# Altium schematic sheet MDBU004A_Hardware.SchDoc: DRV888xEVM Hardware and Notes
size 431 x 279 mm; Date: Not shown in title block; ApprovedBy: Not shown in title block; CheckedBy: Not shown in title block; Author: Not shown in title block; CompanyName: Not shown in title block; DrawnBy: Rick Duncan; Engineer: Not shown in title block; Organization: Not shown in title block; Address1: Not shown in title block; Address2: Not shown in title block; Address3: Not shown in title block; Address4: Not shown in title block; DocumentNumber: 1; Revision: Use project parameter SCH_Rev; SheetNumber: 3; SheetTotal: 3; PageSetup: Record=PageOptions¦CenterHorizontal=True¦CenterVertical=True¦PrintScale=1.00¦XCorrection=1.00¦YCorrection=1.00¦PrintKind=0¦BorderSize=5000000¦LeftOffset=0¦BottomOffset=0¦Orientation=2¦PaperLength=1000¦PaperWidth=1000¦Scale=100¦PaperSource=15¦PrintQuality=600¦MediaType=1¦DitherType=10¦PaperKind=Letter¦PrintScaleMode=1
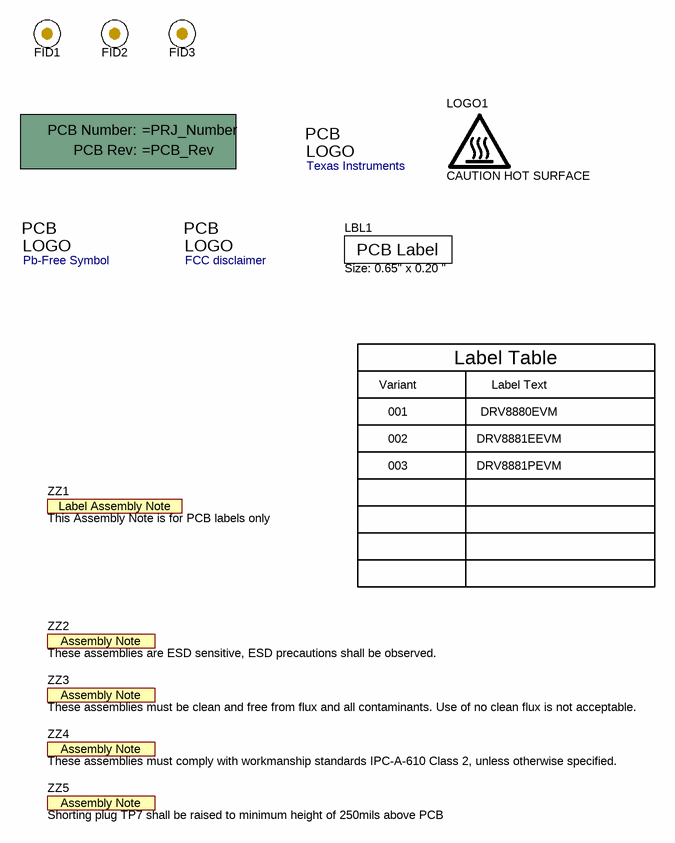
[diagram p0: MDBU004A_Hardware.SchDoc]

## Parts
!PCB1  Printed Circuit Board  (value not drawn)  (mechanical)
FID1  Fiducial  [Fiducial10-20]  (value not drawn)
FID2  Fiducial  [Fiducial10-20]  (value not drawn)
FID3  Fiducial  [Fiducial10-20]  (value not drawn)
LBL1  Size: 0.65" x 0.20 "  [Label_650x200]
LOGO1  CAUTION HOT SURFACE  [IEC_HotSurface_Small]  (no BOM)
Logo2  Texas Instruments  [TI_Symbol_Overlay_Small]  (no BOM)
Logo3  Pb-Free Symbol  [Pb-Free_Overlay_Medium]  (no BOM)
Logo4  FCC disclaimer  [FCC_disclaimer_stacked]  (no BOM)
ZZ1  This Assembly Note is for PCB labels only  [AssemblyNoteLabel]  (no BOM)
ZZ2  These assemblies are ESD sensitive, ESD precautions shall be observed.  [AssemblyNote]  (no BOM)
ZZ3  These assemblies must be clean and free from flux and all contaminants. Use of no clean flux is not acceptable.  [AssemblyNote]  (no BOM)
ZZ4  These assemblies must comply with workmanship standards IPC-A-610 Class 2, unless otherwise specified.  [AssemblyNote]  (no BOM)
ZZ5  Shorting plug TP7 shall be raised to minimum height of 250mils above PCB  [AssemblyNote]  (no BOM)

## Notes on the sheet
- Variant
- 001
- Label Table
- Label Text
- DRV8880EVM
- 002
- 003
- DRV8881EEVM
- DRV8881PEVM

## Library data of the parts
!PCB1 = PCB: Manufacturer: Any; SymbolCreator: a0412235
FID1-FID3 = Fiducial: Fiducial mark.  There is nothing to buy or mount.; SymbolCreator: codlsc
LBL1 = THT-14-423-10: Thermal Transfer Printable Labels, 0.650" W x 0.200" H - 10,000 per roll; Manufacturer: Brady; SymbolCreator: a0412235; CompType: Label
LOGO1 = IEC_HotSurface: IEC 61010-1 Hot Surface Warning; SymbolCreator: a0412235
Logo2 = TI_Logo: Texas Instrument Corporate Signature; SymbolCreator: a0412235
Logo3 = Pb-Free: SymbolCreator: a0412235
Logo4 = FCC_disclaimer: SymbolCreator: codlsc
ZZ1 = AssemblyNoteLabel: SymbolCreator: a0412235
ZZ2-ZZ5 = AssemblyNote: SymbolCreator: codlsc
